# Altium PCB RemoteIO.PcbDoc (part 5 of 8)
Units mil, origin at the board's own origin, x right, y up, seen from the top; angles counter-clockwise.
Board outline 7874.02 x 2362.2 mil, 6 copper layers (Top Layer, GND1, Layer 2, PWR, GND2, Bottom Layer), stack 60.956 mil thick; 655 components, 447 nets, 2607 pads, 1444 vias.
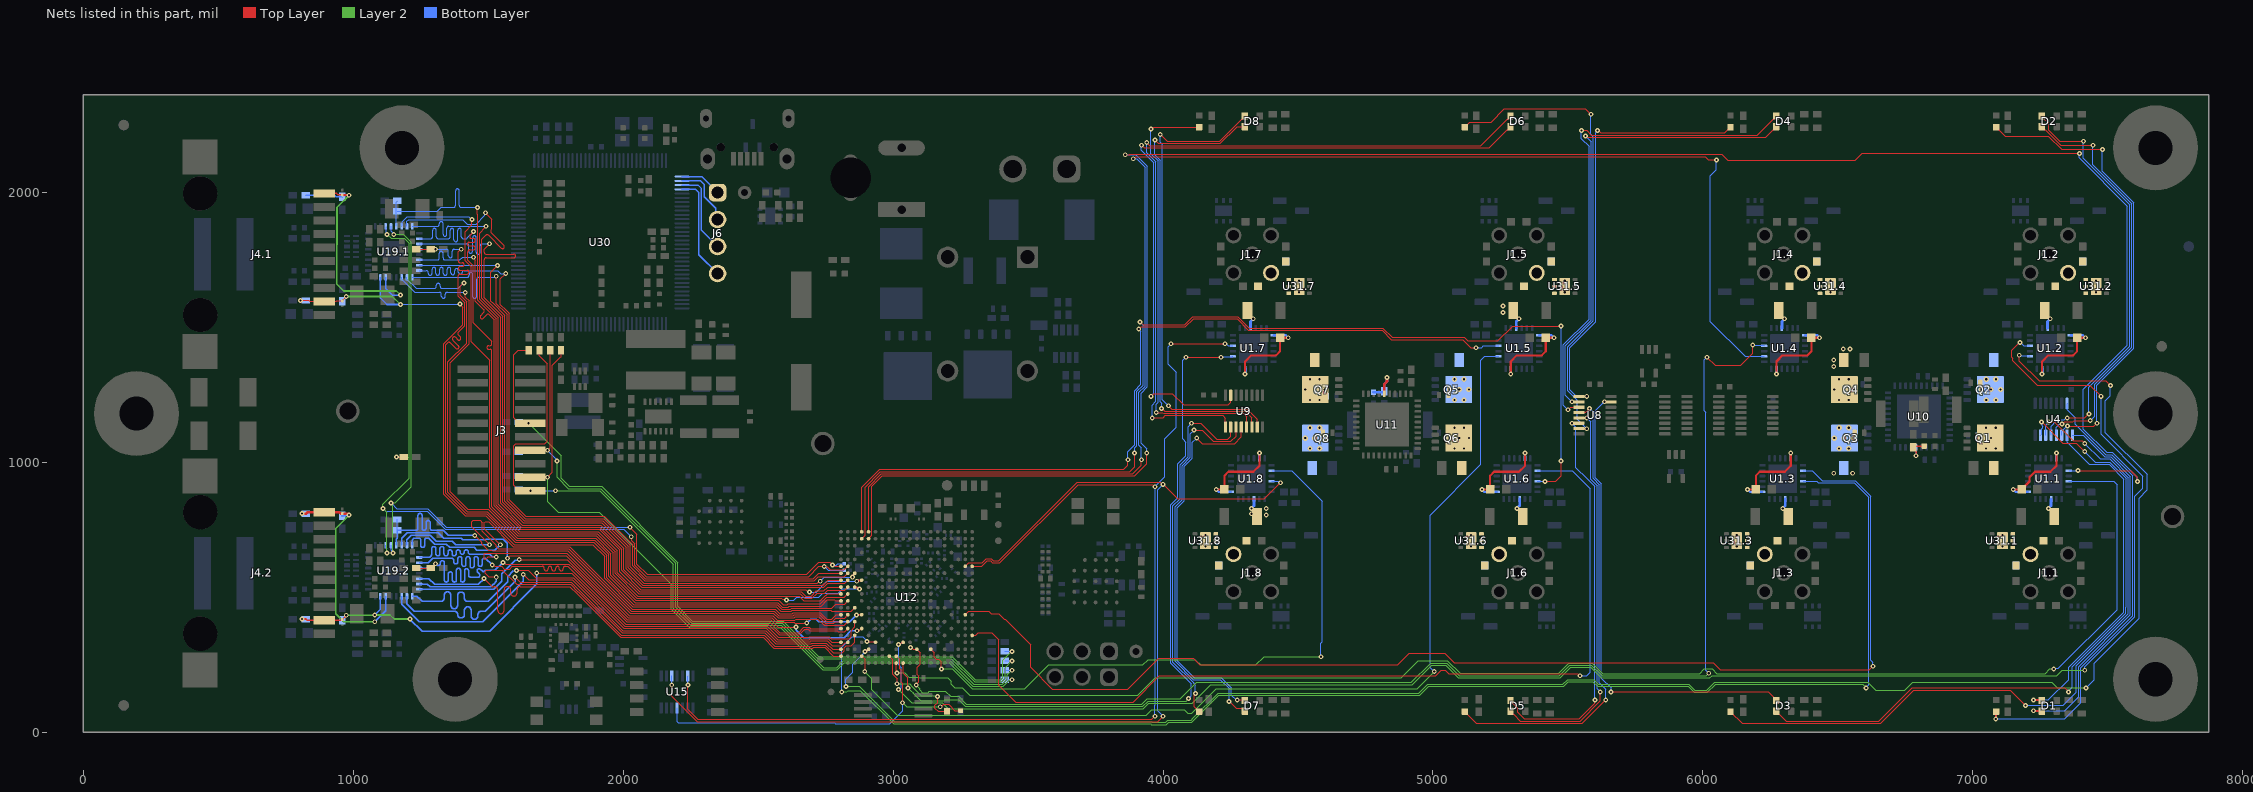
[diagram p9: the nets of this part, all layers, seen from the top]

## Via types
v1: diameter 18, hole 8, Top Layer to Bottom Layer, tented both sides, 1277 vias
v2: diameter 19.68, hole 7.87, Top Layer to Bottom Layer, tented both sides, 133 vias
v3: diameter 19.68, hole 7.87, Top Layer to Bottom Layer, 34 vias

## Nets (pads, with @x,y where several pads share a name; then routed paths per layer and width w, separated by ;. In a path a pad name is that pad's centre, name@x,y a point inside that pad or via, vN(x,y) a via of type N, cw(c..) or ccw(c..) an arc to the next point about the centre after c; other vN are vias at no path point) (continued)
IO_RX1: U1.1.2 U12.W16 | length 7758.4
  Top Layer w4: U12.W16@2909.25,717.52 2921.64,729.91 2921.64,911.64 2960,950 3895,950 3940,995 v1(3940,1035) ; v1(3860,2140) 3876,2140 3877,2141 6070.31,2141 6091.31,2120 6565,2120 6590,2145 v1(7395,2145) ; v1(7390,970) 7585,970 7610,945 v1(7610,930)
  Bottom Layer w4: v1(3860,2140) 3898.69,2140 3942,2096.69 3942,1279.63 3919,1256.63 3919,1071 3940,1050 v1(3940,1035) ; U1.1.2@7355.3,969.53 7355.53,969.76 7389.76,969.76 v1(7390,970) ; v1(7395,2145) 7395,2127.98 7573,1949.98 7573,1434.31 7410,1271.31 7410,1122.63 7495.63,1037 7517.2,1037 7609.2,945 7609.2,930.8 v1(7610,930)
IO_RX2: U1.2.2 U12.C16 | length 6676.2
  Top Layer w4: v1(7171.92,1396.92) 7171.92,1375.71 7245.63,1302 7493,1302 v1(7510,1285)
  Top Layer w6: v1(2896.28,299.1) 2898.28,299.1 2907.25,308.07 U12.C16@2909.25,308.07
  Layer 2 w4: v1(2825,170) 2875,170 3000,45 3005,40 3957.47,40 3960.47,37 4009.53,37 4017.53,45 4103.84,45 4112.84,54 4203.84,145 4947.63,145 4980.63,178 5481.63,178 5498.63,195 5596.12,195 5613.12,178 5948.47,178 5970.47,156 6013.81,156 6043.81,186 6611.47,186 6640.47,157 6748.31,157 6777.31,186 7292.79,186 7313.79,165 v1(7420,165)
  Bottom Layer w4: v1(2825,170) 2825,197.12 2850,222.12 2850,252.82 v1(2896.28,299.1) ; v1(7171.92,1396.92) 7174.04,1394.8 7209.51,1394.8 U1.2.2@7211.63,1392.68 ; v1(7420,165) 7450,195 7450,256.26 7616,422.26 7616,868 7646,898 7646,955.41 7491,1110.41 7491,1228.47 7510,1247.47 v1(7510,1285)
IO_RX3: U1.3.2 U12.H2 | length 4565.4
  Top Layer w4: U12.H2@3267.52,436.02 3279.91,448.41 3355,448.41 3363.41,440 3391.79,440 3412.79,419 3414.94,419 3510,323.94 3510,240.58 3590.58,160 3870,160 3985,275 4111.31,275 4136.31,250 4870,250 4913,293 5043.57,293 5078.57,258 6037.81,258 6063.81,232 6617,232 v1(6630,245)
  Bottom Layer w4: U1.3.2@6371.04,969.53 6405.47,969.53 6443,932 6564.31,932 6622,874.31 6622,268 6630,260 v1(6630,245)
IO_RX4: U1.4.2 U12.Y16 | length 5413.5
  Top Layer w4: U12.Y16@2909.25,743.11 2909.25,910.57 2956.69,958 3888,958 3920,990 v1(3920,1010) ; v1(3890,2125) 3891.34,2125 3899.34,2133 6008.21,2133 6019.25,2121.96 6048.04,2121.96 v1(6050,2120)
  Bottom Layer w4: v1(3890,2125) 3890.28,2124.72 3902.66,2124.72 3934,2093.37 3934,1282.94 3911,1259.94 3911,1064 3920,1055 v1(3920,1010) ; v1(6050,2120) 6050,2083.79 6028,2061.79 6028,1522.15 6157.48,1392.68 U1.4.2@6227.38,1392.68
IO_RX5: U1.5.2 U12.B17 | length 3650.4
  Top Layer w4: U12.B17@2883.66,282.48 2896.05,270.09 2896.05,226.05 v1(2895,225)
  Layer 2 w4: v1(2895,225) 2921,199 2921,157.94 3014.94,64 3937.69,64 3957.69,84 4078.53,84 4082.85,79.68 4092.53,70 4106.21,70 4197.21,161 4941,161 v1(5005,225)
  Bottom Layer w4: v1(5005,225) 4990,240 4990,805 5178,993 5178,1378 5192.68,1392.68 U1.5.2@5243.13,1392.68
IO_RX6: U1.6.2 U12.E1 | length 3465.2
  Top Layer w4: U12.E1@3293.11,359.25 3306.52,359.25 3316.12,368.84 3366.16,368.84 3392,343 3392,175 3455,112 3889.88,112 3986.88,209 4965.31,209 4966.31,210 5011.21,210 5031.21,230 5046.21,230 5058.21,218 5535.66,218 5543.66,210 v1(5545,210)
  Bottom Layer w4: U1.6.2@5386.79,969.53 5516.79,969.53 5583,903.31 5583,223 5570,210 v1(5545,210)
IO_RX7: U1.7.2 U12.A11 | length 2691
  Top Layer w4: U12.A11@3037.2,256.89 3038,256.09 3038,219.62 3055,202.62 v1(3055,165) ; v1(4085,1390) v1(4215,1390)
  Layer 2 w4: v1(3055,165) 3065,155 3066.21,155 3075,146.21 3075,145 3102,118 3189.02,118 3191.02,120 3244.24,120 3268.24,96 3875,96 3924.43,96 3944.43,116 4086,116 v1(4095,125)
  Bottom Layer w4: v1(4085,1390) 4073,1378 4073,1087 4085,1075 4085,1025 4055,995 4055,868.43 4029,842.43 4029,256 4105,180 4105,135 v1(4095,125) ; v1(4215,1390) 4216.34,1391.34 4257.54,1391.34 U1.7.2@4258.88,1392.68
IO_RX8: U1.8.2 U12.C7 | length 2409.6
  Top Layer w4: U12.C7@3139.57,308.07 3151.96,295.68 3151.96,278.16 3160.03,270.09 3169.48,270.09 3178.36,261.21 3178.36,236.64 v1(3180,235)
  Layer 2 w4: v1(3180,235) 3219.75,235 3293.75,161 3488,161 3577,250 3925,250 3945,270 4120,270 4140,250 4344.27,250 4374.27,280 v1(4585,280)
  Bottom Layer w4: U1.8.2@4402.54,969.53 4476.79,969.53 4525.66,920.66 4590,856.31 4590,334.9 4585,329.9 v1(4585,280)
IO_TX1: U1.1.4 U12.A12 | length 5462.6
  Top Layer w4: U12.A12@3011.61,256.89 3011.61,227.75 3015,224.36 v1(3015,220.57)
  Layer 2 w4: v1(3015,220.57) 3043.21,220.57 3058.79,205 3095.58,205 3098.58,202 3203,202 3215,190 3215,178.79 3228.79,165 3255.8,165 3283.8,137 3907,137 3972,202 4882,202 4945,265 4988.69,265 5053.94,265 5100.57,218.37 5465.43,218.37 5504.06,257 5590.69,257 5629.69,218 5988,218 6005,235 6035,235 6052,218 7268,218 7285,235 v1(7300,235)
  Bottom Layer w4: v1(7300,235) 7302.68,237.68 7317.42,237.68 7535,455.25 7535,917 7521.84,930.16 U1.1.4@7355.3,930.16
IO_TX2: U1.2.4 U12.D11 | length 6426.2
  Top Layer w4: v1(3020.22,325.45) 3022.9,328.12 3029.02,328.12 3034.56,333.66 U12.D11@3037.2,333.66 ; v1(7175,1445) 7173.79,1445 7145,1416.21 7145,1390 7148.92,1386.08 7148.92,1376.08 7239,1286 7434,1286 v1(7475,1245)
  Layer 2 w4: v1(3020,158.58) 3033.43,145.15 3033.64,145.15 3068.79,110 3182.39,110 3204.39,88 3614.57,88 3927.75,88 3947.75,108 4108,108 4177,177 4923.31,177 4995.31,249 5047.31,249 5094.31,202 5471.69,202 5510.69,241 5584.06,241 5623.06,202 6025.87,202 6033.87,210 7311.21,210 7331.21,230 v1(7415,230)
  Bottom Layer w4: v1(3020,158.58) 3021.42,160 3025,160 3030,165 3030,240 3020.22,249.78 v1(3020.22,325.45) ; v1(7175,1445) 7187.95,1432.05 U1.2.4@7211.63,1432.05 ; v1(7415,230) 7415,243.89 7600,428.89 7600,874.63 7630,904.63 7630,948.79 7475,1103.79 v1(7475,1245)
IO_TX3: U1.3.4 U12.D15 | length 5241
  Top Layer w4: v1(2904,337.3) 2905.82,335.48 2933.02,335.48 U12.D15@2934.84,333.66
  Layer 2 w4: v1(2810,150) 2828.79,150 2833.79,155 2878.69,155 2998.69,35 3001.69,32 3954.16,32 3957.16,29 4012.84,29 4020.84,37 4107.15,37 4207.15,137 4950.94,137 4983.94,170 5484.94,170 5501.94,187 5592.81,187 5609.81,170 5945.16,170 5967.16,148 6017.12,148 6047.12,178 6592,178 v1(6605,165)
  Bottom Layer w4: v1(2810,150) 2810,315.51 2848.99,354.5 2886.8,354.5 v1(2904,337.3) ; U1.3.4@6371.04,930.16 6422.15,930.16 6428.31,924 6561,924 6614,871 6614,177.21 6605,168.21 v1(6605,165)
IO_TX4: U1.4.4 U12.C9 | length 4724.1
  Top Layer w4: v1(3065.07,314.41) 3068.86,314.41 3075.19,308.07 U12.C9@3088.39,308.07 3100.78,295.68 3100.78,251.76 3090,240.98 3090,214.3 3095,209.3 3095,187.43 3085.8,178.22 v1(3085.8,175.42) ; v1(6015,1390) 6045,1360 6141.21,1360 6185,1403.79 6185,1430 v1@6180,1435
  Layer 2 w4: v1(3085.8,175.42) 3098.63,162.58 3098.63,157.16 3108.79,147 3129.79,147 3134.79,152 3194.21,152 3213.21,133 3242.55,133 3270.55,105 3922.12,105 3941.12,124 4064,124 4125,185 4920,185 4992,257 5050.63,257 5097.25,210.37 5468.75,210.37 5507.37,249 5587.38,249 5626.38,210 6012.65,210 v1(6021.65,219)
  Bottom Layer w4: v1(6015,1390) 6005,1380 6005,1191.63 6010,1186.63 6010,230.65 v1(6021.65,219) ; v1(6185,1435) 6186.48,1433.52 6225.91,1433.52 U1.4.4@6227.38,1432.05
IO_TX5: U1.5.4 U12.Y17 | length 3109.1
  Top Layer w4: U12.Y17@2883.66,743.11 2883.66,907.6 2950.06,974 3854,974 3870,990 v1(3870,1010) ; v1(3910,1495) 3912.1,1495 3919.34,1502.24 3922.66,1502.24 3922.9,1502 4083.31,1502 4113.31,1532 4274.34,1532 4316.34,1490 4811.31,1490 4846.31,1455 5110.25,1455 5140.25,1425 v1(5160,1425)
  Bottom Layer w4: v1(3870,1010) 3870,1040 3895,1065 3895,1266.57 3918,1289.57 3918,1485.66 3910,1493.66 v1(3910,1495) ; v1(5160,1425) 5180,1425 5187.05,1432.05 U1.5.4@5243.13,1432.05
IO_TX6: U1.6.4 U12.W17 | length 4067.4
  Top Layer w4: U12.W17@2883.66,717.52 2896.05,729.91 2896.05,908.68 2953.37,966 3876,966 3895,985 v1(3895,1035) ; v1(3915,1520) 3916.21,1520 3926.21,1510 4080,1510 4110,1540 4277.66,1540 4319.66,1498 4814.63,1498 4849.63,1463 5116.42,1463 5129.42,1450 5240,1450 5295,1505 v1(5475,1505) ; v1(5415,930) 5455,930 5475,950 v1(5475,1005)
  Bottom Layer w4: v1(3895,1035) 3895,1053.69 3903,1061.69 3903,1263.25 3926,1286.25 3926,1509 v1(3915,1520) ; U1.6.4@5386.79,930.16 5386.87,930.08 5414.92,930.08 v1(5415,930) ; v1(5475,1005) v1(5475,1505)
IO_TX7: U1.7.4 U12.R1 U15.6 | length 4348.8
  Top Layer w4: v1(2240,176) 2240,85 2277,48 3957.96,48 v1(3970,60) ; U12.R1@3293.11,615.16 3328.94,615.16 3348.79,635 3361.21,635 3368.21,628 3395.63,628 3685.63,918 3962,918 v1(3970,910) ; v1(4030,1440) v1(4230,1440)
  Bottom Layer w4: U15.6@2239.37,209.06 2239.69,208.74 2239.69,176.31 v1(2240,176) ; v1(3970,60) 3970,100 3972,102 3972,908 v1(3970,910) 3970,910.21 4007,947.21 4007,1088.31 4049,1130.31 4049,1334.79 4020,1363.79 4020,1428.79 4030,1438.79 v1(4030,1440) ; v1(4230,1440) 4233.51,1440 4241.46,1432.05 U1.7.4@4258.88,1432.05
IO_TX8: U1.8.4 U12.R2 U15.3 | length 4204.9
  Top Layer w4: v1(2180,175) 2180,133.69 2273.69,40 3980,40 v1(4000,60) ; U12.R2@3267.52,615.16 3279.91,627.55 3330.02,627.55 3345.47,643 3364.53,643 3371.53,636 3392.31,636 3661.81,905.5 3682.31,926 3989.21,926 3996.21,919 v1(4000,919) 4054,865 4375,865 v1(4435,925)
  Bottom Layer w4: v1(2180,175) 2180.16,175.16 2180.16,208.9 U15.3@2180.32,209.06 ; v1(4000,60) 3980,80 3980,898.79 4000,918.79 v1(4000,919) ; U1.8.4@4402.54,930.16 4426.05,930.16 4431.21,925 v1(4435,925)
JTAG_TCK: J3.11 R147.1 R151.1 R203.1 | length 2832.8
  Top Layer w4: v1(1650,1145) 1614,1145 1602,1157 1602,1158 1594,1166 1594,1399 1611.38,1416.38 R203.1@1650,1416.38
  Layer 2 w4: v1(1650,1145) 1770,1025 1770,941.31 1800.31,911 1920.31,911 2202,629.31 2202,466.69 2256.69,412 2593,412 2724.5,280.5 3219.5,280.5 3305,195 3398.69,195 3407,203.31 3407,267 v1(3440,300)
  Bottom Layer w4: R147.1@1613.62,1150 v1@1650,1150 ; R151.1@3413.62,300 v1(3440,300)
JTAG_TDI: J3.3 R148.1 R152.1 R212.1 | length 2869.2
  Top Layer w4: J3.3@1656.5,945 v1(1720,945) 1738,963 1738,1360.34 1767.66,1390 1770,1392.34 R212.1@1770,1416.38
  Layer 2 w4: v1(1720,945) 1720,855 1759,816 1911.63,816 2178,549.63 2178,456.75 2246.75,388 2583.06,388 2739.06,232 2793.82,232 2819.32,257.5 3208.56,257.5 3225.1,240.96 3295.06,171 3408.63,171 3429.95,192.32 3437.32,192.32 v1(3440,195)
  Bottom Layer w4: R148.1@1613.62,950 1690,950 1695,945 v1(1720,945) ; R152.1@3413.62,195 v1(3440,195)
JTAG_TDO: J3.7 R149.1 R153.1 R205.1 | length 2838.3
  Top Layer w4: J3.7@1656.5,1045 v1(1720,1045) 1730,1055 R205.1@1730,1416.38
  Layer 2 w4: v1(1755,1005) 1755,945 1797,903 1917,903 2194,626 2194,463.37 2253.37,404 2589.69,404 2721.19,272.5 3216.19,272.5 3301.69,187 3402,187 3415,200 3415,240 v1(3440,265)
  Bottom Layer w4: R149.1@1613.62,1040 1695,1040 1700,1045 v1(1720,1045) 1720,1042.5 1755,1007.5 v1(1755,1005) ; R153.1@3413.62,265 v1(3440,265)
JTAG_TMS: J3.1 R150.1 R154.1 R204.1 | length 2997.7
  Top Layer w4: v1(1656.5,895) 1614,895 1594,915 1594,1061.48 1602.52,1070 1710.47,1070 1719.54,1079.06 1719.54,1365.46 1690,1395 R204.1@1690,1416.38
  Layer 2 w4: v1(1750,895) 1913.69,895 2186,622.69 2186,460.06 2250.06,396 2586.37,396 2691.19,291.19 2742.37,240 2790.51,240 2815.51,265 3212.37,265 3298.37,179 3405.31,179 3423,196.69 3423,213 v1(3440,230)
  Bottom Layer w4: R150.1@1613.62,900 1647.71,900 1652.71,895 v1(1656.5,895) v1(1750,895) ; R154.1@3413.62,230 v1(3440,230)
L+1: C1.1.2 C14.2 J1.1.1 Q1.5 Q1.6 Q1.7 Q1.8 Q1.9 R155.2 RV1.1.2 RV2.1.2 RV3.1.2 U1.1.9 U31.1.1 U31.1.2 U31.1.3 U31.1.7@7110,710 | length 38.8
  Bottom Layer w10: v1(7280,830) 7289.84,839.84 U1.1.9@7289.84,864.7
  other v2: 7049.25,1051.61 7084.88,1051.61 7031.44,1090 7067.07,1090 7049.25,1128.39 7084.88,1128.39
  other v3: 7110,688.35 7110,731.65
L+2: C1.2.2 C13.2 J1.2.1 Q2.5 Q2.6 Q2.7 Q2.8 Q2.9 R156.2 RV1.2.2 RV2.2.2 RV3.2.2 U1.2.9 U31.2.1 U31.2.2 U31.2.3 U31.2.7@7456.93,1652.2 | length 38.8
  Bottom Layer w10: U1.2.9@7277.09,1497.5 7277.09,1522.36 v1(7286.93,1532.2)
  other v2: 7049.65,1231.61 7085.28,1231.61 7031.83,1270 7067.46,1270 7103.09,1270 7049.65,1308.39 7085.28,1308.39
  other v3: 7456.93,1630.55 7456.93,1673.86
L+3: C1.3.2 C12.2 J1.3.1 Q3.5 Q3.6 Q3.7 Q3.8 Q3.9 R157.2 RV1.3.2 RV2.3.2 RV3.3.2 U1.3.9 U31.3.1 U31.3.2 U31.3.3 U31.3.7@6125.75,710 | length 38.8
  Bottom Layer w10: v1(6295.75,830) 6305.59,839.84 U1.3.9@6305.59,864.7
  other v1: 6485,960 6555,960
  other v2: 6504.72,1051.61 6540.35,1051.61 6486.91,1090 6522.54,1090 6558.17,1090 6504.72,1128.39 6540.35,1128.39
  other v3: 6125.75,688.35 6125.75,731.65
L+4: C1.4.2 C11.2 J1.4.1 Q4.5 Q4.6 Q4.7 Q4.8 Q4.9 R158.2 RV1.4.2 RV2.4.2 RV3.4.2 U1.4.9 U31.4.1 U31.4.2 U31.4.3 U31.4.7@6472.68,1652.2 | length 38.8
  Bottom Layer w10: U1.4.9@6292.83,1497.5 6292.83,1522.36 v1(6302.68,1532.2)
  other v1: 6485,1355 6485,1380 6520,1420 6545,1420
  other v2: 6504.72,1231.61 6540.35,1231.61 6486.91,1270 6522.54,1270 6558.17,1270 6504.72,1308.39 6540.35,1308.39
  other v3: 6472.68,1630.55 6472.68,1673.86
L+5: C1.5.2 C19.2 J1.5.1 Q5.5 Q5.6 Q5.7 Q5.8 Q5.9 R159.2 RV1.5.2 RV2.5.2 RV3.5.2 U1.5.9 U31.5.1 U31.5.2 U31.5.3 U31.5.7@5488.43,1652.2 | length 38.8
  Bottom Layer w10: U1.5.9@5308.58,1497.5 5308.58,1522.36 v1(5318.43,1532.2)
  other v1: 5260,1555 5260,1580
  other v2: 5079.65,1231.61 5115.28,1231.61 5061.83,1270 5097.46,1270 5133.09,1270 5079.65,1308.39 5115.28,1308.39
  other v3: 5488.43,1630.55 5488.43,1673.86
L+6: C1.6.2 C18.2 J1.6.1 Q6.5 Q6.6 Q6.7 Q6.8 Q6.9 R160.2 RV1.6.2 RV2.6.2 RV3.6.2 U1.6.9 U31.6.1 U31.6.2 U31.6.3 U31.6.7@5141.5,710 | length 38.8
  Bottom Layer w10: v1(5311.5,830) 5321.34,839.84 U1.6.9@5321.34,864.7
  other v2: 5079.65,1051.61 5115.28,1051.61 5061.83,1090 5097.46,1090 5133.09,1090 5079.65,1128.39 5115.28,1128.39
  other v3: 5141.5,688.35 5141.5,731.65
L+7: C1.7.2 C17.2 J1.7.1 Q7.5 Q7.6 Q7.7 Q7.8 Q7.9 R161.2 RV1.7.2 RV2.7.2 RV3.7.2 U1.7.9 U31.7.1 U31.7.2 U31.7.3 U31.7.7@4504.17,1652.2 | length 38.8
  Bottom Layer w10: U1.7.9@4324.33,1497.5 4324.33,1522.36 v1(4334.17,1532.2)
  other v2: 4544.72,1231.61 4580.35,1231.61 4526.91,1270 4562.54,1270 4598.17,1270 4544.72,1308.39 4580.35,1308.39
  other v3: 4504.17,1630.55 4504.17,1673.86
L+8: C1.8.2 C16.2 J1.8.1 Q8.5 Q8.6 Q8.7 Q8.8 Q8.9 R162.2 RV1.8.2 RV2.8.2 RV3.8.2 U1.8.9 U31.8.1 U31.8.2 U31.8.3 U31.8.7@4157.24,710 | length 38.8
  Bottom Layer w10: v1(4327.24,830) 4337.09,839.84 U1.8.9@4337.09,864.7
  other v1: 4382.24,805 4327.24,810 4382.24,830
  other v2: 4544.72,1051.61 4580.35,1051.61 4526.91,1090 4562.54,1090 4598.17,1090 4544.72,1128.39 4580.35,1128.39
  other v3: 4157.24,688.35 4157.24,731.65
LED1: D9.1 U4.15 | length 1669.1
  Top Layer w8: v1(7085,50) 7085.81,50.81 7085.81,75.96 D9.1@7086.61,76.77
  Bottom Layer w4: v1(7085,50) 7340,50 7400,110 7400,240 7407,247 7407,247.2 7592,432.2 7592,435.79 7592,950.88 7513.88,1029 7492.31,1029 7380,1141.31 7380,1165 7350.27,1194.73 7350.27,1218 U4.15@7349.21,1219.06
LED2: D1.2 U4.1 | length 1393.7
  Top Layer w8: v1(7225,80) 7225.63,79.37 7255.28,79.37 D1.2@7255.91,78.74
  Bottom Layer w4: v1(7225,80) 7340,80 7392,132 7392,243.52 7584,435.51 7584,439.16 7584,947.57 7510.57,1021 7489,1021 7409.06,1100.94 U4.1@7368.9,1100.94
LED3: D1.1 U4.2 | length 1317.6
  Top Layer w8: v1@7220,120 v1(7225,120) 7254.02,120 D1.1@7255.91,118.11
  Bottom Layer w4: v1(7225,120) 7280,120 7355,195 7355,241.31 7559,445.31 7559,938.63 7504.63,993 7432,993 7349.84,1075.16 U4.2@7349.84,1100.32
  Bottom Layer w8: U4.2@7349.21,1100.94 U4.2@7349.84,1100.32
LED4: D10.1 U4.3 | length 1705
  Top Layer w4: D10.1@7086.61,2242.13 7119.37,2209.37 7279.32,2209.37 7328.69,2160 v1(7480,2160) ; v1(7350.49,1134.81) 7448.98,1134.81 7459.17,1145 v1(7460,1145)
  Bottom Layer w4: U4.3@7329.53,1100.94 7329.53,1115.71 7348.63,1134.81 v1(7350.49,1134.81) ; v1(7460,1145) 7460,1286.31 7597,1423.31 7597,1961.69 7480,2078.69 v1(7480,2160)
LED5: D2.2 U4.4 | length 1528.4
  Top Layer w4: D2.2@7255.91,2244.09 7255.91,2242.13 7265.72,2232.32 7267.68,2232.32 7325,2175 v1(7445,2175) ; v1(7330,1142.83) 7333.79,1142.83 7340.96,1150 7370,1150 7375,1155 v1(7435,1155)
  Bottom Layer w4: U4.4@7309.84,1100.94 7309.84,1129.84 7324.76,1144.76 7328.07,1144.76 v1(7330,1142.83) ; v1(7435,1155) 7452,1172 7452,1289.63 7589,1426.63 7589,1958.37 7445,2102.37 v1(7445,2175)
LED6: D2.1 U4.5 | length 1545.5
  Top Layer w4: D2.1@7255.91,2283.46 7255.91,2281.5 7280.68,2256.72 7280.68,2230.63 7321.31,2190 v1(7410,2190) ; v1(7350,1165) 7415,1165 v1(7430,1180)
  Bottom Layer w4: U4.5@7290.16,1100.94 7290.16,1134.89 7310,1154.73 7310,1155.49 7312.34,1157.83 7339.04,1157.83 7346.21,1165 v1(7350,1165) ; v1(7410,2190) 7410,2126.06 7581,1955.06 7581,1431 7533.03,1383.03 7533.03,1381.97 7430,1278.94 v1(7430,1180)
LED7: D11.1 U4.6 | length 2703.2
  Top Layer w4: D11.1@6102.36,76.77 6145.13,34 6659,34 6782,157 7138,157 v1(7195,100) ; v1(7280,1150) 7301.62,1150 7371.62,1080 7405,1080 v1(7415,1070)
  Bottom Layer w4: v1(7195,100) 7335,100 7384,149 7384,246.83 7576,438.83 7576,442.47 7576,944.25 7507.25,1013 7472,1013 v1(7415,1070) ; U4.6@7270.47,1100.94 7270.47,1138.31 7280,1147.84 v1(7280,1150)
LED8: D3.2 U4.7 | length 2489.3
  Top Layer w4: D3.2@6271.65,78.74 6271.65,76.78 6281.46,66.97 6283.43,66.97 6308.39,42 6652,42 6775,165 7340,165 v1(7355,150) ; v1(7255,1150) 7333,1072 7383,1072 v1(7415,1040)
  Bottom Layer w4: U4.7@7250.79,1100.94 7254.69,1104.85 7254.69,1124.69 7258.49,1128.49 7258.49,1134.72 7257.68,1135.53 7257.68,1147.32 v1(7255,1150) ; v1(7355,150) 7355,153.34 7369,167.34 7369,244 7567,442 7567,448 7567.5,448.5 7567.5,464.5 7568,465 7568,940.94 7507.94,1001 7454,1001 v1(7415,1040)
LED9: D3.1 U8.15 | length 1763.9
  Top Layer w4: v1(5635,1225) 5635.79,1224.21 U8.15@5659.06,1224.21 ; v1(5660,150) 6241.73,150 6271.65,120.07 D3.1@6271.65,118.11
  Bottom Layer w4: v1(5635,1225) 5601,1191 5601,944.25 5624,921.25 5624,201 5660,165 v1(5660,150)
LED10: D12.1 U8.1 | length 1610.8
  Top Layer w4: U8.1@5540.94,1243.9 5541.5,1244.45 5569.45,1244.45 v1(5570,1245) ; v1(5610,2230) 5613.21,2230 5622.21,2221 6081.24,2221 D12.1@6102.36,2242.13
  Bottom Layer w4: v1(5570,1245) 5531.31,1245 5507,1269.31 5507,1425.69 5602.32,1521.01 5602.32,2220.66 5610,2228.34 v1(5610,2230)
LED11: D4.2 U8.2 | length 1795.6
  Top Layer w4: v1(5515,1225) 5515.39,1224.61 5540.55,1224.61 U8.2@5540.94,1224.21 ; v1(5565,2210) 5568.79,2210 5573.79,2205 6232.56,2205 6259.88,2232.32 6261.84,2232.32 6271.65,2242.13 D4.2@6271.65,2244.09
  Bottom Layer w4: v1(5515,1225) 5491,1249 5491,1432.31 5586.32,1527.64 5586.32,2188.68 v1(5565,2210)
LED12: D4.1 U8.3 | length 1897.4
  Top Layer w4: v1(5500,1195) 5501.69,1195 5511.45,1204.76 5540.71,1204.76 U8.3@5540.94,1204.53 ; v1(5550,2230) 5570,2230 5587,2213 6201.19,2213 6259.88,2271.69 6261.84,2271.69 6271.65,2281.5 D4.1@6271.65,2283.46
  Bottom Layer w4: v1(5500,1195) 5483,1212 5483,1435.63 5578.32,1530.95 5578.32,2171.68 5550,2200 v1(5550,2230)
LED13: D13.1 U8.4 | length 1725.4
  Top Layer w4: D13.1@5118.11,76.77 5160.88,34 5554,34 v1(5640,120) ; U8.4@5540.94,1184.84 5541.37,1185.27 5565.27,1185.27 v1(5580,1200)
  Bottom Layer w4: v1(5580,1200) 5593,1187 5593,940.94 5616,917.94 5616,184 5640,160 v1(5640,120)
LED14: D5.2 U8.5 | length 1477.9
  Top Layer w4: D5.2@5287.4,78.74 5287.4,76.78 5297.21,66.97 5299.18,66.97 5324.14,42 5545,42 5620,117 v1(5620,150) ; U8.5@5540.94,1165.16 5541.02,1165.08 5569.92,1165.08 v1(5570,1165)
  Bottom Layer w4: v1(5570,1165) 5585,1150 5585,937.63 5608,914.63 5608,178.31 5608,162 v1(5620,150)
LED15: D5.1 U8.6 | length 1473
  Top Layer w4: D5.1@5287.4,118.11 5287.4,116.14 5313.3,90.24 5313.3,75.06 5338.36,50 5541.69,50 5599.24,107.55 5599.24,119.24 v1(5600,120) ; v1(5515,1145) 5515.24,1145.24 5540.71,1145.24 U8.6@5540.94,1145.47
  Bottom Layer w4: v1(5515,1145) 5530,1130 5530,981.31 5570,941.31 5600,911.31 5600,175 v1(5600,120)
LED16: D14.1 U8.7 | length 1770.4
  Top Layer w4: D14.1@5118.11,2242.13 5136.95,2260.97 5215.97,2260.97 5265,2310 5565,2310 v1(5585,2290) ; U8.7@5540.94,1125.79 5541.34,1125.39 5569.61,1125.39 v1(5570,1125)
  Bottom Layer w4: v1(5570,1125) 5535,1160 5535,1230 5499,1266 5499,1429 5594.32,1524.32 5594.32,2205.68 5585,2215 v1(5585,2290)
LED17: D6.2 U9.15 | length 2706.1
  Top Layer w4: v1(3920,2175) 3930,2165 5208.31,2165 5275.63,2232.32 5277.59,2232.32 5287.4,2242.13 D6.2@5287.4,2244.09 ; v1(3955,1245) 3956.21,1245 3966.21,1255 4035,1255 4076,1214 4242.4,1214 4250.79,1222.39 U9.15@4250.79,1249.06
  Bottom Layer w4: v1(3920,2175) 3920,2156.31 3966,2110.31 3966,1256 v1(3955,1245)
LED18: D6.1 U9.1 | length 2750.3
  Top Layer w4: v1(3940,2185) 3951,2174 5177.94,2174 5275.63,2271.69 5277.59,2271.69 5287.4,2281.5 D6.1@5287.4,2283.46 ; v1(3960,1165) 4000,1165 4009,1174 4221,1174 4231.1,1163.9 U9.1@4231.1,1130.94
  Bottom Layer w4: v1(3940,2185) 3940,2147.63 3974,2113.63 3974,1226.53 3960,1212.53 v1(3960,1165)
LED19: D15.1 U9.2 | length 1343.1
  Top Layer w4: v1(4105,1145) 4140,1145 4199,1086 4240,1086 4250.79,1096.79 U9.2@4250.79,1130.94 ; v1@4115,140 4115,95.63 D15.1@4133.86,76.77
  Bottom Layer w4: v1(4105,1145) 4093,1133 4093,1021.69 4063,991.69 4063,865.12 4037,839.12 4037,259.31 4113,183.31 4113,182 4120,175 v1(4120,144.34)
LED20: D7.2 U9.3 | length 1463.4
  Top Layer w4: v1(4115,1120) 4145,1120 4187,1078 4251.69,1078 4270.47,1096.79 U9.3@4270.47,1130.94 ; v1(4245,115) 4271.49,88.51 4293.38,88.51 D7.2@4303.15,78.74
  Bottom Layer w4: v1(4115,1120) 4101,1106 4101,1018.37 4071,988.37 4071,861.8 4045,835.8 4045,262.63 4112.63,195 4212.66,195 4245,162.66 v1(4245,115)
LED21: D7.1 U9.4 | length 1401.2
  Top Layer w4: v1(4125,1090) 4145,1070 4265,1070 4290.16,1095.16 U9.4@4290.16,1130.94 ; v1(4275,120) 4301.26,120 D7.1@4303.15,118.11
  Bottom Layer w4: v1(4125,1090) 4109,1074 4109,1015.06 4079,985.06 4079,858.49 4053,832.49 4053,265.94 4115.94,203 4215.97,203 4253,165.97 4253,138.21 4271.21,120 v1(4275,120)
LED22: D16.1 U9.5 | length 1626.1
  Top Layer w4: v1(3955,2235) 3962.13,2242.13 D16.1@4133.86,2242.13 ; v1(3975,1185) 3999.9,1185 4002.9,1182 4298,1182 4309.84,1170.16 U9.5@4309.84,1130.94
  Bottom Layer w4: v1(3955,2235) 3955,2143.94 3982,2116.94 3982,1223.21 3975,1216.21 v1(3975,1185)
LED23: D8.2 U9.6 | length 1753
  Top Layer w4: v1(3970,2195) 3983,2182 4213,2182 4275.09,2244.09 D8.2@4303.15,2244.09 ; v1(3995,1200) 3996.21,1200 4006.21,1190 4305,1190 4329.53,1165.47 U9.6@4329.53,1130.94
  Bottom Layer w4: v1(3970,2195) 3970,2140.25 3990,2120.25 3990,1225 3995,1220 v1(3995,1200)
LED24: D8.1 U9.7 | length 1760.2
  Top Layer w4: v1(3990,2215) 4015,2190 4209.69,2190 4291.38,2271.69 4293.34,2271.69 4303.15,2281.5 D8.1@4303.15,2283.46 ; v1(4020,1210) 4032.04,1198 4312,1198 4349.21,1160.79 U9.7@4349.21,1130.94
  Bottom Layer w4: v1(3990,2215) 3990,2186.31 3998,2178.31 3998,1232 v1(4020,1210)
LED_Activity.1: D26.1.1 J4.1.1 R167.1.1 R177.1.2 U19.1.30 | length 971
  Top Layer w6: J4.1.1@892.91,1996.65 896.26,2000 899.62,1996.64 938.36,1996.64 943.66,1991.34 D26.1.1@960,1991.34 960.67,1990.67 984.33,1990.67 v1(985,1990)
  Layer 2 w6: v1(985,1990) 940,1945 940,1807.63 939,1806.63 939,1661 965,1635 1160,1635 v1(1175,1620)
  Bottom Layer w6: R177.1.2@823.62,1990 930,1990 935,1985 958.62,1985 R167.1.1@960,1983.62 966.38,1990 v1(985,1990) ; U19.1.30@1120.47,1685.51 1120.47,1644.53 1145,1620 v1(1175,1620)
LED_Activity.2: D26.2.1 J4.2.1 R167.2.1 R177.2.2 U19.2.30 | length 862.4
  Top Layer w10: v1@810.02,810.02 825.02,810.02 830.55,815.55 J4.2.1@892.91,815.55 947.87,815.55 952.68,810.75 959.92,810.75 960,810.67 D26.2.1@960,810.24 960,810.08 960.08,810 980,810 v1(985,805)
  Layer 2 w6: v1(985,805) 935,755 935,440 965,410 v1(1080,410)
  Bottom Layer w6: v1(1080,410) 1120.47,450.47 U19.2.30@1120.47,504.41
  Bottom Layer w10: R167.2.1@960,802.52 962.48,805 v1(985,805)
  other v1: 810,811.1
LED_ERR: D23.2 U12.B12 U15.11 | length 1355.9
  Top Layer w4: U12.B12@3011.61,282.48 3024,270.09 3024,236 3030,230 3030,185 3035,180 v1(3035,110) ; v1(3175,95) 3178.53,95 3187.37,103.84 3205.43,103.84 3228.96,80.32 D23.2@3250,80.32
  Layer 2 w4: v1(3035,110) 3050,95 v1(3175,95)
  Bottom Layer w4: U15.11@2200,90.94 2200,40 2205,35 2783.69,35 2786.69,32 2987,32 3035,80 v1(3035,110)
LED_Link.1: D27.1.1 J4.1.9 R166.1.1 R176.1.2 U12.J18 U19.1.31 | length 3316
  Top Layer w4: v1(805.13,1600) 835,1600 838.35,1596.65 J4.1.9@892.91,1596.65 936.65,1596.65 938.66,1598.66 D27.1.1@960,1598.66 960,1599.25 974.32,1613.57 v1(974.32,1615) ; v1(1396.23,1587.56) 1396.23,1583.9 1405,1575.12 1405,1510 1335,1440 1335,882.37 1415.14,802.24 1490.69,802.24 1596.92,696 1887.69,696 1931,652.69 1931,570.31 2036.31,465 2566.69,465 2583.69,448 2623.22,448 2627.22,452 2769.21,452 2771.99,449.22 2845.68,449.22 U12.J18@2858.07,461.61
  Layer 2 w6: v1(974.32,1615) 1145,1615 v1(1175,1585)
  Bottom Layer w4: v1(805.13,1600) R176.1.2@825,1600 ; R166.1.1@960,1596.38 960,1600.32 974.32,1614.64 v1(974.32,1615) ; v1(1175,1585) 1176.28,1586.28 1392.49,1586.28 v1@1395,1588.79
  Bottom Layer w6: U19.1.31@1100.79,1685.51 1100.79,1609.21 1125,1585 v1(1175,1585)
LED_Link.2: D27.2.1 J4.2.9 R166.2.1 R176.2.2 U12.G18 U19.2.31 | length 2454.1
  Top Layer w4: v1(1680,590) 1809.09,590 2006.09,393 2534.37,393 2575.37,352 2686.21,352 2689.21,355 2762.78,355 2770.92,346.86 2785,346.86 2837.61,346.86 2844.87,354.12 2844.87,359.87 2845,360 2845,377.36 2858.07,390.43 U12.G18@2858.07,410.43
  Top Layer w6: v1(810,420) 825,420 829.45,415.55 J4.2.9@892.91,415.55 958.08,415.55 960,417.47 D27.2.1@960,417.56 960,418.15 974.32,432.47 v1(974.32,434.02)
  Layer 2 w6: v1(974.32,434.02) 974.81,434.51 1079.51,434.51 v1(1080,435) 1136.62,435 1151.62,420 v1(1210,420)
  Bottom Layer w5: v1(1210,420) 1255,375 1505,375 1680,550 v1(1680,590)
  Bottom Layer w6: R166.2.1@960,415.28 960,419.21 974.32,433.54 v1(974.32,434.02) ; v1(1080,435) 1100.79,455.79 U19.2.31@1100.79,504.41
LED_STATUS: D24.2 U12.B13 | length 381.6
  Top Layer w4: U12.B13@2986.02,282.48 2999.22,269.28 2999.22,215.14 3015,199.36 v1(3015,180) ; v1(3165,133) 3165,110 3155,100 3155,90 3166.65,78.35 D24.2@3200,78.35
  Layer 2 w4: v1(3015,180) 3061.21,180 3070,171.21 3070,170 3105,135 3163,135 v1(3165,133)
MDIO.MDC: R114.1 U12.R20 U19.1.12 U19.2.12 | length 3242.3
  Top Layer w4: v1(2025,760) 2051,734 2051,623.2 2089.2,585 2680,585 2724.95,629.95 2765.05,629.95 v1(2775,620) 2778.79,620 2783.63,615.16 U12.R20@2806.89,615.16
  Layer 2 w4: v1(1147,665) 1147,843 v1(1140,850) 1155,850 1215,910 1215,1815 1185,1845 v1(1150,1845)
  Bottom Layer w4: v1(1140,850) 1162,828 1277,828 1345,760 v1(2025,760) ; U19.2.12@1140.16,693.39 1140.16,675.57 1147,668.73 v1(1147,665) ; U19.1.12@1140.16,1874.49 1140.16,1856.37 1150,1846.53 v1(1150,1845) ; v1@2780,620 2790,620 2795,625 R114.1@2818.98,625
MDIO.MDIO: R41.2 R115.1 U12.R19 U19.1.11 U19.2.11 | length 3411.9
  Top Layer w4: v1(1160,1020) R41.2@1186.38,1020 ; v1(2030,725) 2032.08,722.92 2032.08,710 2043,699.08 2043,619.88 2085.88,577 2687,577 2724.95,614.95 v1(2745,614.95) 2746.58,613.37 2756.63,613.37 2768.04,601.96 2819.28,601.96 U12.R19@2832.48,615.16
  Layer 2 w4: v1(1125,665) 1125,815 v1(1110,830) 1110,845 1207,942 1207,1020 ; v1(1125,1845) 1140,1830 1188.69,1830 1207,1811.69 1207,1020 ; v1(1160,1020) 1207,1020
  Bottom Layer w4: v1(1110,830) 1111.21,830 1121.21,820 1273.69,820 1341.69,752 2003,752 v1(2030,725) ; U19.2.11@1120.47,693.39 1120.47,686.5 1125,681.97 v1(1125,665) ; U19.1.11@1120.47,1874.49 1122.74,1872.22 1122.74,1847.26 v1(1125,1845) ; v1@2745,615 v1(2745,614.95) 2759.95,600 R115.1@2818.98,600
MII1_RX_ER: R171.1.1 R181.1.2 U12.K19 U19.1.20 | length 3163.2
  Top Layer w4: R181.1.2@1233.62,1790 R171.1.1@1285,1790 ; R171.1.1@1286.38,1790 v1(1304.87,1790) ; 1389.92,1422.55 cw(c1384.98,1427.5) 1380.03,1422.55 1359.4,1443.18 ccw(c1354.45,1438.23) 1349.5,1443.18 1343,1436.69 1343,1432 1343,885.69 1418.45,810.24 1494,810.24 1600.24,704 1891,704 1939,656 1939,573.63 2039.63,473 2570,473 2587,456 2619.91,456 2623.91,460 2773.28,460 2788.1,474.82 2820.09,474.82 U12.K19@2832.48,487.2 ; 1389.93,1422.55 ccw(c1384.98,1427.5) 1389.92,1432.45 1369.3,1453.08 cw(c1374.24,1458.03) 1369.29,1462.98 cw(c1374.24,1458.03) 1379.19,1462.98 1386.91,1455.27 ccw(c1391.86,1460.22) 1396.81,1455.27 ccw(c1391.86,1460.22) 1396.81,1465.17 1389.09,1472.88 cw(c1394.04,1477.83) 1389.09,1482.78 1405.66,1499.34 1413,1506.69 1413,1592 1389.23,1615.77 1389.23,1675 1389.23,1691 cw(c1396.23,1691) 1396.23,1698 1422,1698 ccw(c1422,1705) 1422,1712 1396.23,1712 cw(c1396.23,1719) 1396.23,1726 1403.69,1726 ccw(c1403.69,1733) 1403.69,1740 1396.23,1740 cw(c1396.23,1747) 1389.23,1747 1389.23,1779.23 1390,1780 v1(1400,1790)
  Bottom Layer w4: U19.1.20@1244.49,1789.84 1244.57,1789.92 1330,1789.92 1346,1789.92 cw(c1346,1782.92) 1353,1782.92 1353,1765.47 ccw(c1360,1765.47) 1367,1765.47 1367,1782.92 cw(c1374,1782.92) 1374,1789.92 1385,1789.92 1399.92,1789.92 v1(1400,1790)
MII1_RXCLK: U12.N20 U19.1.19 | length 3093.4
  Top Layer w4: v1(1505,1810) 1485,1790 1485,1779 ccw(c1492,1779) 1492,1772 1594.54,1772 cw(c1594.54,1765) 1594.54,1758 1492,1758 ccw(c1492,1751) 1485,1751 1485,1735 1485,1611.06 1554,1542.06 1554,852.06 1630.06,776 1920.82,776 2011,685.82 2011,606.63 2072.63,545 2740,545 2758.98,563.98 U12.N20@2806.89,563.98
  Bottom Layer w4: U19.1.19@1244.49,1809.53 1244.72,1809.76 1405,1809.76 1421,1809.76 cw(c1421,1802.76) 1428,1802.76 1428,1782 ccw(c1435,1782) 1442,1782 1442,1832.69 cw(c1449,1832.69) 1456,1832.69 1456,1778.21 ccw(c1463,1778.21) 1470,1778.21 1470,1802.76 cw(c1477,1802.76) 1477,1809.76 1490,1809.76 1504.76,1809.76 v1(1505,1810)
MII1_RXD0: U12.N17 U19.1.16 | length 2974.8
  Top Layer w4: v1@1490,1875 1490,1871 1469,1850 1469,1604.43 1538,1535.43 1538,845.43 1623.43,760 1914.2,760 1995,679.2 1995,600 2066,529 2662.31,529 2677.21,529 2686.21,520 v1(2690,520)
  Top Layer w6: v1(2865.2,559.8) 2868.45,559.8 2871.14,562.49 2882.17,562.49 U12.N17@2883.66,563.98
  Bottom Layer w4: U19.1.16@1218.9,1874.49 1219.41,1875 1310,1875 1312,1875 ccw(c1312,1882) 1319,1882 1319,1885 cw(c1326,1885) 1333,1885 1333,1845.18 ccw(c1340,1845.18) 1347,1845.18 1347,1868 cw(c1354,1868) 1354,1875 1410,1875 v1(1492,1875) ; v1(2690,520) 2715,520 2754.8,559.8 v1(2865.2,559.8)
MII1_RXD1: U12.N19 U19.1.15 | length 3092.3
  Top Layer w4: v1@1495,1925 1494.57,1924.57 1494.57,1920.43 1513.34,1901.66 1513.34,1886.66 1513.34,1863.34 1511.11,1861.11 ccw(c1516.06,1856.16) 1511.11,1851.21 1558.43,1803.89 cw(c1553.48,1798.94) 1558.43,1793.99 cw(c1553.48,1798.94) 1548.53,1793.99 1501.21,1841.31 ccw(c1496.26,1836.36) 1491.31,1841.31 1480,1830 1477,1827 1477,1607.74 1546,1538.74 1546,848.75 1626.75,768 1917.51,768 2003,682.51 2003,603.31 2069.31,537 2743.31,537 2757.9,551.59 2820.09,551.59 U12.N19@2832.48,563.98
  Bottom Layer w4: U19.1.15@1199.21,1874.49 1199.21,1894.21 1205,1900 1405,1900 1422,1883 1455,1883 1487.32,1915.32 1487.32,1922.32 v1(1490,1925)
MII1_RXD2: U12.M18 U19.1.14 | length 3000
  Top Layer w4: v1(1440,1900) 1440,1880 1415,1855 1415,1747 1437,1725 1437,1448 1506,1379 1506,832.18 1610.18,728 1900.94,728 1963,665.94 1963,584.63 2050.63,497 2586.31,497 2590.64,492.68 2602.32,492.68 v1(2605,490)
  Top Layer w6: U12.M18@2858.07,538.39 2859.56,536.9 2866.52,536.9 2872.07,531.34 v1(2875.32,531.34)
  Bottom Layer w4: U19.1.14@1179.53,1874.49 1182.3,1877.26 1182.3,1892.3 1200,1910 1428.79,1910 1438.79,1900 v1(1440,1900) ; v1(2605,490) 2632.34,490 2642.34,500 2725,500 2740,515 2797.6,515 2813.94,531.34 v1(2875.32,531.34)
MII1_RXD3: R172.1.1 R182.1.2 U12.M20 U19.1.13 | length 3134.8
  Top Layer w4: v1(1460,1945) 1460,1920 1461,1919 1461,1601.12 1530,1532.12 1530,842.12 1620.12,752 1910.88,752 1987,675.88 1987,595.63 2061.63,521 2659,521 2675.77,504.23 2696.21,504.23 2715.98,524 2744,524 2758.39,538.39 U12.M20@2806.89,538.39
  Bottom Layer w4: U19.1.13@1159.84,1874.49 1159.84,1964.84 R172.1.1@1165,1970 ; R182.1.2@1163.62,1930 1311.19,1930 1326.19,1945 1370,1945 1372,1945 ccw(c1372,1952) 1379,1952 1379,2006.35 cw(c1386,2006.35) 1393,2006.35 1393,1952 ccw(c1400,1952) 1400,1945 1435,1945 v1(1460,1945)
MII1_RXDV: U12.L20 U19.1.18 | length 3092.8
  Top Layer w4: v1@1445,1855 1445,1854 1432.95,1841.95 ccw(c1437.9,1837) 1437.9,1830 1446,1830 cw(c1446,1823) 1446,1816 1430,1816 ccw(c1430,1809) 1430,1802 1446,1802 cw(c1446,1795) 1446,1788 1432,1788 ccw(c1432,1781) 1425,1781 1425,1765 1425,1748.31 1445,1728.31 1445,1518.48 1514,1449.48 1514,1440 cw(c1507,1440) 1507,1433 1502.4,1433 ccw(c1502.4,1426) 1502.4,1419 1507,1419 cw(c1507,1412) 1514,1412 1514,1410 1514,835.49 1613.49,736 1904.25,736 1971,669.25 1971,589 2055,505 2652.37,505 2669.14,488.23 2730.61,488.23 2750.37,508 2753,508 2757.8,512.8 U12.L20@2806.89,512.8
  Bottom Layer w4: U19.1.18@1244.49,1829.21 1285,1829.21 1287,1829.21 ccw(c1287,1836.21) 1294,1836.21 1294,1860 cw(c1301,1860) 1308,1860 1308,1836.21 ccw(c1315,1836.21) 1315,1829.21 1325,1829.21 1350,1829.21 1352,1829.21 ccw(c1352,1836.21) 1359,1836.21 1359,1860 cw(c1366,1860) 1373,1860 1373,1824.76 ccw(c1380,1824.76) 1387,1824.76 1387,1860 cw(c1394,1860) 1401,1860 1401,1836.21 ccw(c1408,1836.21) 1408,1829.21 1420.21,1829.21 1425,1834 v1(1446,1855)
MII1_TXCLK: U12.M19 U19.1.22 | length 2775.9
  Top Layer w4: v1(1446,1760) 1446,1757 1453,1750 1453,1597.8 1460.4,1590.4 1484.19,1566.62 cw(c1479.24,1561.67) 1484.19,1556.72 1471.79,1544.32 ccw(c1476.74,1539.37) 1471.79,1534.42 ccw(c1476.74,1539.37) 1481.69,1534.42 1494.09,1546.82 cw(c1499.04,1541.87) 1503.99,1546.82 1505.4,1545.4 1522,1528.8 1522,838.8 1616.8,744 1907.57,744 1979,672.57 1979,592.31 2058.31,513 2655.69,513 2672.45,496.23 2699.53,496.23 2719.29,516 2747.31,516 2757.31,526 2820.09,526 U12.M19@2832.48,538.39
  Bottom Layer w4: U19.1.22@1244.49,1750.47 1310,1750.47 1312,1750.47 ccw(c1312,1757.47) 1319,1757.47 1319,1774.92 cw(c1326,1774.92) 1333,1774.92 1333,1757.47 ccw(c1340,1757.47) 1340,1750.47 1370,1750.47 1395.47,1750.47 1405,1760 v1@1445,1760
MII1_TXD0: U12.P20 U19.1.24 | length 2776.9
  Top Layer w4: v1(1565,1700) 1545,1680 1545,1585 1565,1565 1578,1552 1578,862 1640,800 1920,800 1930.76,800 2035,695.76 2035,616.57 2082.57,569 2704.13,569 2724.69,589.57 U12.P20@2806.89,589.57
  Bottom Layer w4: U19.1.24@1244.49,1711.1 1255,1711.1 1271,1711.1 cw(c1271,1704.1) 1278,1704.1 1278,1700.51 ccw(c1285,1700.51) 1292,1700.51 1292,1715.39 cw(c1299,1715.39) 1306,1715.39 1306,1700.51 ccw(c1313,1700.51) 1320,1700.51 1320,1715.39 cw(c1327,1715.39) 1334,1715.39 1334,1700.51 ccw(c1341,1700.51) 1348,1700.51 1348,1715.39 cw(c1355,1715.39) 1362,1715.39 1362,1702.37 ccw(c1369,1702.37) 1376,1702.37 1376,1711.1 cw(c1383,1711.1) 1390,1711.1 1390,1704.1 ccw(c1397,1704.1) 1404,1704.1 cw(c1411,1704.1) 1411,1711.1 1430,1711.1 1535.11,1711.1 1546.21,1700 v1(1565,1700)
MII1_TXD1: U12.P19 U19.1.25 | length 2777.6
  Top Layer w4: v1(1530,1690) 1530,1588.69 1565,1553.69 1570,1548.69 1570,858.69 1636.69,792 1916.14,792 1927.45,792 2027,692.45 2027,613.25 2079.25,561 2707.44,561 2722.81,576.37 2819.28,576.37 U12.P19@2832.48,589.57
  Bottom Layer w4: U19.1.25@1218.9,1685.51 1420,1685.51 1422,1685.51 ccw(c1422,1692.51) 1429,1692.51 1429,1696.1 cw(c1436,1696.1) 1443,1696.1 1443,1614.7 ccw(c1450,1614.7) 1457,1614.7 1457,1678.51 cw(c1464,1678.51) 1464,1685.51 1505,1685.51 1521.72,1685.51 1526.21,1690 v1(1530,1690)
MII1_TXD2: U12.K20 U19.1.26 | length 2777.9
  Top Layer w4: v1(1410,1665) 1397.23,1652.23 1397.23,1619.09 1421,1595.31 1421,1442.31 1351,1372.31 1351,889 1421.76,818.24 1497.31,818.24 1603.55,712 1894.31,712 1947,659.31 1947,578 2044,481 2573.31,481 2590.31,464 2611.63,464 2615.63,468 2733,468 2757,492 2782.22,492 2787.02,487.2 U12.K20@2806.89,487.2
  Bottom Layer w4: U19.1.26@1199.21,1685.51 1199.21,1678.62 1232.83,1645 1270,1645 1301,1645 ccw(c1301,1652) 1308,1652 1308,1656.38 cw(c1315,1656.38) 1322,1656.38 1322,1652 ccw(c1329,1652) 1329,1645 1345,1645 1390,1645 v1(1410,1665)
MII1_TXD3: U12.L19 U19.1.27 | length 2777.9
  Top Layer w4: v1(1415,1630) 1415,1612.63 1429,1598.63 1429,1439 1359,1369 1359,892.31 1425.08,826.24 1500.63,826.24 1606.86,720 1897.63,720 1955,662.63 1955,581.31 2047.31,489 2576.63,489 2593.63,472 2608.31,472 2612.31,476 2729.69,476 2753.69,500 2819.68,500 U12.L19@2832.48,512.8
  Bottom Layer w4: U19.1.27@1179.53,1685.51 1179.53,1678.62 1228.15,1630 1290,1630 1320,1630 cw(c1320,1623) 1327,1623 1327,1615.58 ccw(c1334,1615.58) 1341,1615.58 1341,1623 cw(c1348,1623) 1348,1630 1350,1630 v1(1415,1630)
MII1_TXEN: U12.P18 U19.1.23 | length 2684
  Top Layer w4: v1(1535,1730) 1510,1705 1510,1597.37 1516.19,1591.19 1562,1545.37 1562,855.37 1633.37,784 1924.14,784 2019,689.14 2019,609.94 2075.94,553 2710.75,553 2719.73,553 2726.73,560 v1(2730,560)
  Top Layer w6: v1(2850,575) 2852.3,577.3 2852.3,581.69 2858.07,587.46 U12.P18@2858.07,589.57
  Bottom Layer w4: U19.1.23@1244.49,1730.79 1244.88,1730.39 1534.61,1730.39 v1(1535,1730) ; v1(2730,560) 2745,575 2785,575 v1(2850,575)
MII2_RX_ER: R171.2.1 R181.2.2 U12.F20 U19.2.20 | length 2127.7
  Top Layer w4: R181.2.2@1233.62,608.9 R171.2.1@1286.38,608.9 1290.32,608.9 1305,623.58 v1(1305,625) ; v1(1555,630) 1557.34,630 1564.34,623 1798.72,623 1810.83,610.89 2012.72,409 2541,409 2580,370 2650,370 2670,390 2690,390 2695.16,384.84 U12.F20@2806.89,384.84
  Bottom Layer w5: U19.2.20@1244.49,608.74 1288.74,608.74 v1(1305,625) 1309.7,620.3 ccw(c1315,625.61) 1322.5,625.61 1322.5,628.5 cw(c1330,628.5) 1337.5,628.5 1337.5,564.5 ccw(c1345,564.5) 1352.5,564.5 1352.5,587 cw(c1360,587) 1367.5,587 1367.5,564.5 ccw(c1375,564.5) 1382.5,564.5 1382.5,600.42 cw(c1390,600.42) 1397.5,600.42 1397.5,564.5 ccw(c1405,564.5) 1412.5,564.5 1412.5,598.59 cw(c1420,598.59) 1427.5,598.59 1427.5,582.5 ccw(c1435,582.5) 1435,575 1455,575 1465,575 1466.77,576.77 ccw(c1461.46,582.07) 1466.77,587.37 1460.84,593.3 cw(c1466.15,598.6) 1460.84,603.91 cw(c1466.15,598.6) 1471.45,603.91 1477.37,597.98 ccw(c1482.68,603.28) 1487.98,597.98 1490,600 1519.06,600 1525,600 v1(1555,630)
MII2_RXCLK: U12.F19 U19.2.19 | length 2021.8
  Top Layer w4: v1(1515,620) 1518.79,620 1523.79,615 1550,615 1560,605 1580,605 1590,615 1685,615 1701,615 cw(c1701,608) 1708,608 1708,605 ccw(c1715,605) 1722,605 1722,608 cw(c1729,608) 1736,608 1736,605 ccw(c1743,605) 1750,605 1750,608 cw(c1757,608) 1764,608 1764,605 ccw(c1771,605) 1778,605 1778,608 cw(c1785,608) 1785,615 1795.41,615 1802.83,607.58 2009.41,401 2537.69,401 2577.69,361 2652.31,361 2673.31,382 2686.69,382 2691.84,376.84 2793.16,376.84 2797.55,372.45 2820.09,372.45 U12.F19@2832.48,384.84
  Bottom Layer w5: U19.2.19@1244.49,628.43 1278.86,628.43 1295.44,645 1317.72,645 1365.22,645 cw(c1365.22,637.5) 1372.72,637.5 1372.72,631.7 ccw(c1380.22,631.7) 1387.72,631.7 1387.72,643.5 cw(c1395.22,643.5) 1402.72,643.5 1402.72,622.59 ccw(c1410.22,622.59) 1417.72,622.59 1417.72,643.5 cw(c1425.22,643.5) 1432.72,643.5 1432.72,616.71 ccw(c1440.22,616.71) 1447.72,616.71 1447.72,643.5 cw(c1455.22,643.5) 1462.72,643.5 1462.72,622.6 ccw(c1470.22,622.6) 1477.72,622.6 1477.72,637.5 cw(c1485.22,637.5) 1485.22,645 1490,645 1514.73,620.27 v1(1515,620)
MII2_RXD0: U12.H20 U19.2.16 | length 2018.8
  Top Layer w4: v1(1545,695) 1486.29,753.71 1486.29,777.66 1488.63,780 1501.61,780 1593.61,688 1802,688 2033,457 2563.37,457 2580.37,440 2626.53,440 2630.53,444 2731,444 2755,420 2773.5,420 2789.53,436.02 U12.H20@2806.89,436.02
  Bottom Layer w5: U19.2.16@1218.9,693.39 1218.9,712.19 1225,718.29 1226.71,720 1242.5,720 cw(c1242.5,712.5) 1250,712.5 1250,693 ccw(c1257.5,693) 1265,693 1265,712.5 cw(c1272.5,712.5) 1272.5,720 1280,720 1302.5,697.5 1345,697.5 1357.5,685 1447.5,685 1457.5,675 1525,675 v1(1545,695)
MII2_RXD1: U12.H19 U19.2.15 | length 2044.2
  Top Layer w4: v1(1505,695) 1465,735 1465,736.21 1440,761.21 1440,780 1445,785 1470,785 1478.29,776.71 1478.29,745.4 1530,693.69 1530,686.84 1536.84,680 1798.29,680 2029.29,449 2560.06,449 2577.06,432 2629.85,432 2633.85,436 2727.69,436 2751.69,412 2776.82,412 2788.45,423.63 2820.09,423.63 U12.H19@2832.48,436.02
  Bottom Layer w5: U19.2.15@1199.21,693.39 1199.21,714.21 1215,730 1285,730 1307.5,707.5 1367.5,707.5 1380,695 v1(1505,695)
MII2_RXD2: U12.H17 U19.2.14 | length 1938.7
  Top Layer w4: v1(1571.09,645) 1581.09,655 1789.35,655 1826.83,617.52 2019.35,425 2550.12,425 2567.12,408 2633.31,408 2636.31,405 v1(2680,405)
  Top Layer w6: v1(2865,435) 2865.51,435.51 2883.15,435.51 U12.H17@2883.66,436.02
  Bottom Layer w5: U19.2.14@1179.53,693.39 1179.53,719.53 1199.9,739.9 1315.1,739.9 1335,720 1400.46,720 1405.96,714.5 1491.42,714.5 1491.92,715 1555,715 1570,700 1570,646.09 v1(1571.09,645) ; v1(2680,405) 2694.78,419.78 2715,419.78 2724.78,410 2840,410 v1(2865,435)
MII2_RXD3: R172.2.1 R182.2.2 U12.G20 U19.2.13 | length 2063.8
  Top Layer w4: v1(1450,730) 1476.34,703.66 1476.34,698.66 1500,675 1513.69,675 1516.69,672 1794.98,672 2025.98,441 2556.75,441 2573.75,424 2633.16,424 2637.16,428 2724.37,428 2748.37,404 2780.13,404 2786.56,410.43 U12.G20@2806.89,410.43
  Bottom Layer w4: R182.2.2@1163.62,748.9 R172.2.1@1163.62,788.9
  Bottom Layer w5: U19.2.13@1159.84,693.39 1159.84,714.84 1163.62,718.62 R182.2.2@1163.62,748.9 1230,748.9 1232.5,748.9 ccw(c1232.5,756.4) 1240,756.4 1240,804 cw(c1247.5,804) 1255,804 1255,756.4 ccw(c1262.5,756.4) 1270,756.4 1270,777.51 cw(c1277.5,777.51) 1285,777.51 1285,756.4 ccw(c1292.5,756.4) 1292.5,748.9 1320,748.9 1332.77,748.9 1351.67,730 v1(1450,730)
MII2_RXDV: U12.G19 U19.2.18 | length 2018.3
  Top Layer w4: v1(1530,650) 1500,650 1490.66,640.66 1487.34,640.66 1485,643 1485,661.66 1487.34,664 1791.66,664 2022.66,433 2553.43,433 2570.43,416 2636.48,416 2640.48,420 2721.06,420 2745.06,396 2783.44,396 2784.68,397.23 2819.28,397.23 U12.G19@2832.48,410.43
  Bottom Layer w5: U19.2.18@1244.49,648.11 1283.11,648.11 1285,650 1287.5,652.5 ccw(c1278.45,661.55) 1291.25,661.55 1291.25,681 cw(c1298.75,681) 1306.25,681 1306.25,661.5 ccw(c1313.75,661.5) 1321.25,661.5 1321.25,681 cw(c1328.75,681) 1336.25,681 1336.25,661.5 ccw(c1343.75,661.5) 1351.25,661.5 1351.25,668.5 cw(c1358.75,668.5) 1366.25,668.5 1366.25,661.5 ccw(c1373.75,661.5) 1381.25,661.5 1381.25,668.5 cw(c1388.75,668.5) 1396.25,668.5 1396.25,667.5 ccw(c1403.75,667.5) 1411.25,667.5 1411.25,668.5 cw(c1418.75,668.5) 1426.25,668.5 1426.25,667.5 ccw(c1433.75,667.5) 1433.75,660 1445,660 1505,660 1515,650 v1(1530,650)
MII2_TXCLK: U12.B20 U19.2.22 | length 1930.8
  Top Layer w4: v1(1485,570) 1515,540 1523,540 cw(c1523,528) 1535,528 1535,452 ccw(c1547,452) 1559,452 1559,528 cw(c1571,528) 1583,528 1583,516.96 ccw(c1595,516.96) 1607,516.96 1607,528 cw(c1619,528) 1619,540 1650,540 1802.37,540 1829.37,513 1829.53,513 1990.53,352 2518.8,352 2558.8,312 2702.78,312 2705.78,315 2746.21,315 2778.73,282.48 U12.B20@2806.89,282.48
  Bottom Layer w5: U19.2.22@1244.49,569.37 1280.63,569.37 1302,548 1463,548 v1(1485,570)
MII2_TXD0: U12.F17 U19.2.24 | length 1840
  Top Layer w4: v1(1615,640) 1793.04,640 1802.04,631 1818.83,614.2 2016.04,417 2546.8,417 2573.8,390 v1(2640,390)
  Top Layer w6: v1(2866.39,376.77) 2868.69,379.06 2875.78,379.06 2881.56,384.84 U12.F17@2883.66,384.84
  Bottom Layer w4: v1@1612.5,637.5 v1(1615,640)
  Bottom Layer w5: U19.2.24@1244.49,530 1520,530 1550,560 1550,587.5 1600,637.5 v1@1612.5,637.5 ; v1(2640,390) 2641.67,388.33 2641.67,378.33 2668.5,351.5 2785,351.5 2818.74,351.5 2844,376.77 v1(2866.39,376.77)
MII2_TXD1: U12.D20 U19.2.25 | length 1920.9
  Top Layer w4: v1(1605,600) 1648.79,600 1675.79,573 1814.78,573 2002.78,385 2531.06,385 2572.06,344 2689.53,344 2692.53,347 2759.47,347 2772.81,333.66 2785,333.66 U12.D20@2806.89,333.66
  Bottom Layer w4: 1593.39,598.39 1603.39,598.39 v1(1605,600)
  Bottom Layer w5: U19.2.25@1218.9,504.41 1235.59,504.41 1255,485 1321.88,485 1324.38,485 ccw(c1324.38,497.5) 1336.88,497.5 1336.88,508.5 cw(c1349.38,508.5) 1361.88,508.5 1361.88,470.5 ccw(c1374.38,470.5) 1386.88,470.5 1386.88,507.31 cw(c1399.38,507.31) 1411.88,507.31 1411.88,497.5 ccw(c1424.38,497.5) 1424.38,485 1500,485 1572.5,557.5 1572.5,577.5 1593.39,598.39
MII2_TXD2: U12.C20 U19.2.26 | length 1920.9
  Top Layer w4: v1(1600,575) 1618,557 1808,557 1836,529 1836.15,529 1996.15,369 2524.43,369 2565.43,328 2696.15,328 2699.15,331 2752.84,331 2775.77,308.07 2785,308.07 U12.C20@2806.89,308.07
  Bottom Layer w5: U19.2.26@1199.21,504.41 1199.21,475.79 1210,465 1226,449 1348.75,449 1374.5,449 cw(c1374.5,436.5) 1387,436.5 ccw(c1399.5,436.5) 1412,436.5 1412,452.69 cw(c1424.5,452.69) 1437,452.69 1437,431.5 ccw(c1449.5,431.5) 1462,431.5 1462,436.5 cw(c1474.5,436.5) 1474.5,449 1477,449 1489,449 1600,560 v1(1600,575)
MII2_TXD3: U12.D19 U19.2.27 | length 1913
  Top Layer w4: v1(1630,585) 1650,565 1811.47,565 1999.47,377 2527.75,377 2568.75,336 2692.84,336 2695.84,339 2756.15,339 2773.88,321.27 2785,321.27 2812.02,321.27 2823.33,332.58 2831.4,332.58 U12.D19@2832.48,333.66
  Bottom Layer w5: U19.2.27@1179.53,504.41 1179.53,475.47 1245,410 1480,410 1630,560 v1(1630,585)
MII2_TXEN: U12.E18 U19.2.23 | length 1913
  Top Layer w4: v1(1530,575) 1527.66,577.34 1502.66,577.34 1490,590 1490,597.66 1492.34,600 1553,600 1605,548 1805.69,548 1832.69,521 1832.84,521 1993.84,360 2522.12,360 2562.12,320 2699.47,320 2702.47,323 2749.53,323 2777.53,295 2785,295 2811.34,295 2819.68,303.34 2819.68,312.8 2827.35,320.46 2845.03,320.46 2858.07,333.5 U12.E18@2858.07,359.25
  Bottom Layer w5: U19.2.23@1244.49,549.68 1275,549.68 1285.68,539 1509,539 1519.68,549.68 1520.32,549.68 1530,559.37 v1(1530,575)
MSP432_SWCLK: J6.4 U30.100 | length 395.8
  Bottom Layer w6: U30.100@2218.15,2011.85 2268.15,2011.85 2280,2000 2280,1770 J6.4@2350,1700
MSP432_SWDIO: J6.3 U30.99 | length 316.9
  Bottom Layer w6: U30.99@2218.15,2027.6 2277.4,2027.6 2290,2015 2290,1860 J6.3@2350,1800
MSP432_TDI: J6.2 U30.98 | length 238.1
  Bottom Layer w6: U30.98@2218.15,2043.35 2286.65,2043.35 2300,2030 2300,1984.65 2343.17,1941.48 2343.17,1906.83 J6.2@2350,1900
MSP432_TDO: J6.1 U30.97 | length 156.3
  Bottom Layer w6: U30.97@2218.15,2059.09 2290.91,2059.09 J6.1@2350,2000
NetC2.1_2: C2.1.2 U1.1.13 U1.1.23 | length 331.1
  Top Layer w8: v1(7150,900) C2.1.2@7180.47,900 7210,929.53 7210,945.31 7214.69,950 7215,950 7230.46,965.46 7287.39,965.46 7310,988.07 v1(7310,1035)
  Bottom Layer w8: v1(7150,900) 7159.21,890.79 U1.1.13@7204.7,890.79 ; U1.1.23@7309.53,1015.3 7309.53,1034.53 v1(7310,1035)
NetC2.2_2: C2.2.2 U1.2.13 U1.2.23 | length 351.2
  Top Layer w8: v1(7256.93,1327.2) 7256.93,1374.13 7279.54,1396.74 7371.93,1396.74 ; 7371.93,1397.2 7386.46,1411.73 C2.2.2@7386.46,1462.2 v1(7416.93,1462.2)
  Bottom Layer w8: v1(7256.93,1327.2) 7257.4,1327.68 U1.2.23@7257.4,1346.91 ; U1.2.13@7362.22,1471.42 7407.72,1471.42 v1(7416.93,1462.2)
NetC2.3_2: C2.3.2 U1.3.13 U1.3.23 | length 351.2
  Top Layer w8: v1(6165.75,900) C2.3.2@6196.22,900 6196.22,950.47 6210.75,965 ; 6210.75,965.46 6303.14,965.46 6325.75,988.07 v1(6325.75,1035)
  Bottom Layer w8: v1(6165.75,900) 6174.96,890.79 U1.3.13@6220.45,890.79 ; U1.3.23@6325.28,1015.3 6325.28,1034.53 v1(6325.75,1035)
NetC2.4_2: C2.4.2 U1.4.13 U1.4.23 | length 351.2
  Top Layer w8: v1(6272.68,1327.2) 6272.68,1374.13 6295.29,1396.74 6387.68,1396.74 ; 6387.68,1397.2 6402.2,1411.73 C2.4.2@6402.2,1462.2 v1(6432.68,1462.2)
  Bottom Layer w8: v1(6272.68,1327.2) 6273.15,1327.68 U1.4.23@6273.15,1346.91 ; U1.4.13@6377.97,1471.42 6423.46,1471.42 v1(6432.68,1462.2)
NetC2.5_2: C2.5.2 U1.5.13 U1.5.23 | length 351.2
  Top Layer w8: v1(5288.43,1327.2) 5288.43,1374.13 5311.03,1396.74 5403.43,1396.74 ; 5403.43,1397.2 5417.95,1411.73 C2.5.2@5417.95,1462.2 v1(5448.43,1462.2)
  Bottom Layer w8: v1(5288.43,1327.2) 5288.9,1327.68 U1.5.23@5288.9,1346.91 ; U1.5.13@5393.72,1471.42 5439.21,1471.42 v1(5448.43,1462.2)
NetC2.6_2: C2.6.2 U1.6.13 U1.6.23 | length 351.2
  Top Layer w8: v1(5181.5,900) C2.6.2@5211.97,900 5211.97,950.47 5226.5,965 ; 5226.5,965.46 5318.89,965.46 5341.5,988.07 v1(5341.5,1035)
  Bottom Layer w8: v1(5181.5,900) 5190.71,890.79 U1.6.13@5236.2,890.79 ; U1.6.23@5341.02,1015.3 5341.02,1034.53 v1(5341.5,1035)
NetC2.7_2: C2.7.2 U1.7.13 U1.7.23 | length 351.2
  Top Layer w8: v1(4304.17,1327.2) 4304.17,1374.13 4326.78,1396.74 4419.17,1396.74 ; 4419.17,1397.2 4433.7,1411.73 C2.7.2@4433.7,1462.2 v1(4464.17,1462.2)
  Bottom Layer w8: v1(4304.17,1327.2) 4304.65,1327.68 U1.7.23@4304.65,1346.91 ; U1.7.13@4409.47,1471.42 4454.96,1471.42 v1(4464.17,1462.2)
NetC2.8_2: C2.8.2 U1.8.13 U1.8.23 | length 351.2
  Top Layer w8: v1(4197.24,900) C2.8.2@4227.72,900 4227.72,950.47 4242.24,965 ; 4242.24,965.46 4334.63,965.46 4357.24,988.07 v1(4357.24,1035)
  Bottom Layer w8: v1(4197.24,900) 4206.46,890.79 U1.8.13@4251.95,890.79 ; U1.8.23@4356.77,1015.3 4356.77,1034.53 v1(4357.24,1035)
NetC15_2: C15.2 R32.2 U10.6 | length 108
  Top Layer w6: v1(6790,1025) 6790,1040.11 6788.81,1041.3 6788.81,1047.57 R32.2@6780,1056.38 6783.94,1060.32 C15.2@6820,1060.32
  Bottom Layer w4: v1(6790,1025) 6790.08,1025.08 6790.08,1055.75 U10.6@6790.16,1055.83
NetC20_2: C20.2 R36.2 U11.6 | length 162.2
  Top Layer w10: U11.6@4820.16,1254.17 4820.16,1290.16 4830,1300 v1(4830,1315)
  Bottom Layer w10: C20.2@4780,1260 4780.31,1259.68 4816.06,1259.68 R36.2@4820,1263.62 4820,1290 4830,1300 v1(4830,1315)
